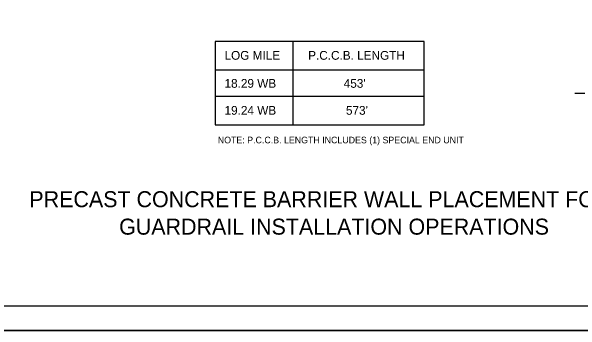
# Model space of a CAD drawing. Extents: x 1397271 to 1411271, y 376395 to 377888.
# Drawn here: x 1409762 to 1410415, y 376395 to 376761 of the extents above; entities that cross this region are included whole.
import ezdxf

# ---------------------------------------------------------------- set-up
doc = ezdxf.new("R2010")
doc.units = 0
for name, color, linetype in [('Default', 7, 'Continuous'), ('R_Border', 7, 'Continuous'), ('R_Border Notes', 7, 'Continuous'), ('R_Draft', 7, 'Continuous'), ('R_No Plot', 7, 'Continuous')]:
    doc.layers.add(name, color=color, linetype=linetype)

msp = doc.modelspace()

# ---------------------------------------------------------------- linework, layer by layer
at = {"layer": 'R_Border'}
msp.add_line((1411238.15, 376422.47), (1409024.85, 376422.47), dxfattribs=at)
at = {"layer": 'R_Border Notes'}
for p, q in [((1410084.48, 376726.24), (1410084.48, 376630.72)), ((1410235.27, 376693.67), (1409995.38, 376693.67)), ((1410235.27, 376663.3), (1409995.38, 376663.3))]:
    msp.add_line(p, q, dxfattribs=at)
msp.add_lwpolyline([(1410235.27, 376726.24), (1409995.38, 376726.24), (1409995.38, 376630.72), (1410235.27, 376630.72)], close=True, dxfattribs=at)
at = {"layer": 'R_Draft'}
msp.add_line((1410407.88, 376667.16), (1410419.25, 376667.16), dxfattribs=at)
at = {"layer": 'R_No Plot'}
msp.add_line((1408938.04, 376394.62), (1411271.41, 376394.62), dxfattribs=at)
for points in [[(1408937.99, 377887.98), (1411271.41, 377887.98), (1411271.41, 376394.59), (1408937.99, 376394.59)], [(1410662.32, 377860.72), (1410662.32, 377791.56), (1410912.44, 377791.56), (1410912.44, 377771.12), (1411074.84, 377771.12), (1411074.84, 377600.79), (1411238.15, 377600.79), (1411238.15, 376422.47), (1409024.85, 376422.47), (1409024.85, 377860.72)]]:
    msp.add_lwpolyline(points, close=True, dxfattribs=at)

# ---------------------------------------------------------------- texts
at = {"layer": 'Default'}
for s, height, p in [('LOG MILE', 10.087, (1410006.25, 376705.43)), ('P.C.C.B. LENGTH', 10.087, (1410102.13, 376705.43)), ('18.29 WB', 10.087, (1410006.25, 376673.28)), ("453'", 10.087, (1410142.92, 376673.28)), ('19.24 WB', 10.087, (1410006.25, 376642.32)), ("573'", 10.087, (1410145.5, 376642.32)), ('PRECAST CONCRETE BARRIER WALL PLACEMENT FOR', 18.3753, (1409782.46, 376536.23)), ('GUARDRAIL INSTALLATION OPERATIONS', 18.3753, (1409885.4, 376504.73))]:
    msp.add_text(s, height=height, dxfattribs=at).set_placement(p)
at = {"layer": 'R_Border'}
msp.add_text('NOTE: P.C.C.B. LENGTH INCLUDES (1) SPECIAL END UNIT', height=7.5652, dxfattribs=at).set_placement((1409998.53, 376609.54))

doc.saveas('drawing.dxf')
